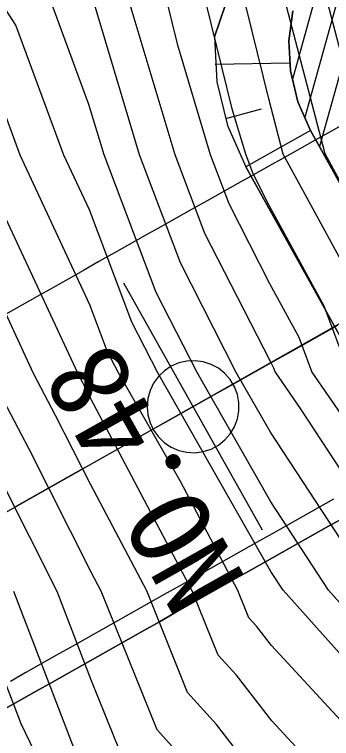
# Model space of a CAD drawing. Extents: x 42655 to 43811, y -141820 to -141156.
# Drawn here: x 43136.65 to 43145.62, y -141417.59 to -141397.14 of the extents above; entities that cross this region are included whole.
import ezdxf

# ---------------------------------------------------------------- set-up
doc = ezdxf.new("R2010")
doc.units = 0
for name, color, linetype in [('D-BMK-HTXT_1', 7, 'Continuous'), ('D-BMK_1', 7, 'Continuous'), ('D-STR', 7, 'Continuous'), ('D-STR-HTXT', 7, 'Continuous'), ('D-STR-STR2トンネル', 7, 'Continuous'), ('ZE_HICN', 7, 'Continuous'), ('ZE_LWCN', 7, 'Continuous'), ('着色', 7, 'Continuous')]:
    doc.layers.add(name, color=color, linetype=linetype)

msp = doc.modelspace()

# ---------------------------------------------------------------- linework, layer by layer
at = {"layer": 'D-BMK-HTXT_1'}
for p, q in [((43274.802, -141333.044), (43130.975, -141414.265)), ((43143.659, -141411.705), (43139.739, -141404.731))]:
    msp.add_line(p, q, dxfattribs=at)
msp.add_lwpolyline([(43140.399, -141408.218), (43140.42, -141408.45), (43140.482, -141408.675), (43140.583, -141408.885), (43140.72, -141409.073), (43140.889, -141409.234), (43141.083, -141409.363), (43141.297, -141409.454), (43141.525, -141409.506), (43141.758, -141409.517), (43141.988, -141409.485), (43142.21, -141409.413), (43142.415, -141409.303), (43142.598, -141409.158), (43142.751, -141408.982), (43142.87, -141408.782), (43142.952, -141408.564), (43142.994, -141408.335), (43142.994, -141408.101), (43142.952, -141407.872), (43142.87, -141407.654), (43142.751, -141407.454), (43142.598, -141407.278), (43142.415, -141407.133), (43142.21, -141407.023), (43141.988, -141406.951), (43141.757, -141406.919), (43141.525, -141406.93), (43141.297, -141406.982), (43141.083, -141407.073), (43140.889, -141407.202), (43140.72, -141407.363), (43140.583, -141407.551), (43140.482, -141407.761), (43140.42, -141407.986), (43140.399, -141408.218)], dxfattribs=at)
at = {"layer": 'D-BMK_1'}
msp.add_lwpolyline([(43145.788, -141405.924), (43145.352, -141406.168), (43144.915, -141406.412), (43144.479, -141406.657), (43144.043, -141406.902), (43143.607, -141407.146), (43143.171, -141407.391), (43142.735, -141407.636), (43142.299, -141407.881), (43141.863, -141408.126), (43141.428, -141408.371), (43140.992, -141408.616), (43140.556, -141408.861), (43140.12, -141409.106), (43139.685, -141409.352), (43139.249, -141409.597), (43138.813, -141409.842), (43138.378, -141410.088), (43137.942, -141410.333), (43137.507, -141410.579), (43137.071, -141410.824), (43136.635, -141411.07)], dxfattribs=at)
at = {"layer": 'D-STR'}
for p, q in [((43144.423, -141398.51), (43142.322, -141398.554)), ((43143.625, -141399.808), (43142.612, -141400.089)), ((43145.025, -141400.418), (43143.191, -141401.439)), ((43145.025, -141400.418), (43150.035, -141409.418)), ((43148.2, -141410.439), (43143.191, -141401.439))]:
    msp.add_line(p, q, dxfattribs=at)
for points in [[(43142.307, -141397.77), (43142.603, -141396.887), (43143.005, -141396.11), (43143.847, -141395.027), (43144.836, -141394.268), (43145.902, -141393.824), (43147.008, -141393.55), (43148.114, -141393.278), (43148.897, -141393.083)], [(43144.518, -141397.037), (43144.404, -141397.881), (43144.451, -141398.732)], [(43142.307, -141397.77), (43142.375, -141399.04), (43142.673, -141400.277), (43143.191, -141401.439)], [(43144.451, -141398.732), (43144.662, -141399.601), (43145.025, -141400.418)]]:
    msp.add_lwpolyline(points, dxfattribs=at)
at = {"layer": 'D-STR-HTXT'}
for p, q in [((43147.177, -141394.04), (43145.277, -141400.87)), ((43146.41, -141394.467), (43144.85, -141400.072)), ((43145.589, -141395.085), (43144.499, -141399.002))]:
    msp.add_line(p, q, dxfattribs=at)
at = {"layer": 'D-STR-STR2トンネル'}
for points in [[(43146.031, -141400.202), (43145.593, -141400.446), (43145.155, -141400.69), (43144.718, -141400.935), (43144.281, -141401.18), (43143.843, -141401.424), (43143.406, -141401.669), (43142.969, -141401.914), (43142.532, -141402.159), (43142.095, -141402.404), (43141.658, -141402.649), (43141.221, -141402.894), (43140.784, -141403.139), (43140.348, -141403.384), (43139.911, -141403.63), (43139.474, -141403.875), (43139.038, -141404.12), (43138.601, -141404.366), (43138.165, -141404.611), (43137.729, -141404.857), (43137.293, -141405.103), (43136.856, -141405.348), (43136.42, -141405.594)], [(43145.674, -141410.83), (43145.239, -141411.074), (43144.804, -141411.319), (43144.368, -141411.563), (43143.933, -141411.808), (43143.498, -141412.053), (43143.062, -141412.297), (43142.627, -141412.542), (43142.192, -141412.787), (43141.757, -141413.032), (43141.322, -141413.277), (43140.886, -141413.523), (43140.451, -141413.768), (43140.016, -141414.013), (43139.581, -141414.258), (43139.146, -141414.504), (43138.71, -141414.749), (43138.275, -141414.995), (43137.84, -141415.24), (43137.405, -141415.486), (43136.97, -141415.731), (43136.534, -141415.977)], [(43145.968, -141411.353), (43145.533, -141411.597), (43145.097, -141411.842), (43144.662, -141412.086), (43144.227, -141412.331), (43143.792, -141412.576), (43143.357, -141412.82), (43142.921, -141413.065), (43142.486, -141413.31), (43142.051, -141413.555), (43141.616, -141413.8), (43141.181, -141414.045), (43140.746, -141414.291), (43140.311, -141414.536), (43139.875, -141414.781), (43139.44, -141415.026), (43139.005, -141415.272), (43138.57, -141415.517), (43138.135, -141415.763), (43137.7, -141416.008), (43137.265, -141416.254), (43136.829, -141416.5), (43136.394, -141416.745)]]:
    msp.add_lwpolyline(points, dxfattribs=at)
at = {"layer": 'ZE_HICN'}
for points in [[(43164.284, -141418.895), (43161.139, -141417.126), (43159.184, -141416.275), (43155.119, -141414.603), (43154.086, -141414.112), (43153.652, -141413.885), (43153.016, -141413.364), (43150.606, -141411.412), (43148.978, -141409.883), (43147.144, -141407.229), (43146.118, -141404.504), (43144.251, -141401.08), (43143.841, -141399.518), (43142.715, -141394.924), (43141.74, -141391.264), (43140.342, -141388.773), (43138.687, -141385.618), (43137.581, -141383.954), (43136.3, -141382.629)], [(43155.333, -141438.004), (43155.812, -141433.818), (43156.43, -141431.836), (43157.209, -141428.129), (43157.365, -141425.669), (43156.075, -141423.318), (43154.119, -141421.235), (43152.664, -141419.528), (43150.124, -141418.199), (43149.012, -141417.289), (43145.534, -141413.399), (43143.894, -141410.906), (43141.811, -141407.254), (43140.654, -141404.988), (43139.181, -141401.104), (43138.753, -141399.676), (43137.543, -141396.396), (43136.607, -141394.953)], [(43145.016, -141438.052), (43145.353, -141433.526), (43145.834, -141431.886), (43146.049, -141429.38), (43146.564, -141425.72), (43145.24, -141424.172), (43143.947, -141422.158), (43143.228, -141420.434), (43141.798, -141418.582), (43140.68, -141417.351), (43139.101, -141413.429), (43138.815, -141412.888), (43137.049, -141409.396), (43135.932, -141407.282)]]:
    msp.add_lwpolyline(points, dxfattribs=at)
at = {"layer": 'ZE_LWCN'}
for points in [[(43164.367, -141436.421), (43166.567, -141431.788), (43167.584, -141429.556), (43169.333, -141425.613), (43168.188, -141420.901), (43167.762, -141419.457), (43164.278, -141417.448), (43161.947, -141416.138), (43159.178, -141414.933), (43155.338, -141413.353), (43154.08, -141412.801), (43151.306, -141410.555), (43148.97, -141408.362), (43148.185, -141407.224), (43146.831, -141403.632), (43145.437, -141401.074), (43143.819, -141394.919), (43142.573, -141390.245), (43141.744, -141388.766), (43138.675, -141382.915), (43138.565, -141382.75), (43138.438, -141382.619), (43137.933, -141381.729), (43134.97, -141376.473)], [(43168.565, -141418.478), (43164.271, -141416.002), (43162.755, -141415.149), (43159.171, -141413.59), (43158.558, -141413.338), (43154.073, -141411.372), (43152.007, -141409.698), (43149.366, -141407.218), (43148.962, -141406.52), (43147.545, -141402.759), (43146.623, -141401.069), (43145.554, -141397), (43144.989, -141394.914), (43144.727, -141393.808), (43143.799, -141390.698), (43143.407, -141389.225), (43143.145, -141388.76), (43142.047, -141386.665), (43140.369, -141382.61)], [(43159.19, -141417.618), (43156.819, -141416.642), (43154.091, -141415.347), (43152.946, -141414.748), (43151.267, -141413.372), (43149.905, -141412.269), (43148.985, -141411.405), (43146.104, -141407.234), (43145.404, -141405.377), (43143.855, -141402.534), (43143.396, -141401.635), (43143.187, -141401.085), (43142.815, -141399.843), (43141.612, -141394.93), (43140.906, -141392.283), (43138.94, -141388.779), (43138.7, -141388.321), (43136.596, -141385.158)], [(43135.612, -141386.361), (43137.226, -141388.787), (43138.712, -141390.877), (43140.073, -141393.302), (43140.508, -141394.935), (43141.25, -141397.965), (43142.185, -141401.09), (43142.71, -141402.473), (43143.865, -141404.735), (43144.691, -141406.25), (43145.063, -141407.239), (43148.992, -141412.926), (43149.204, -141413.126), (43149.519, -141413.38), (43152.241, -141415.611), (43154.097, -141416.582), (43158.519, -141418.682)], [(43135.447, -141388.796), (43138.724, -141393.402), (43139.24, -141394.321), (43139.404, -141394.94), (43139.686, -141396.088), (43141.184, -141401.094), (43142.025, -141403.311), (43143.876, -141406.936), (43143.977, -141407.122), (43144.023, -141407.244), (43144.73, -141408.267), (43148.097, -141413.387), (43148.999, -141414.396), (43151.535, -141416.474), (43154.103, -141417.817), (43157.657, -141419.505), (43158.478, -141420.379), (43159.21, -141421.712), (43161.074, -141425.651), (43160.551, -141427.247), (43159.64, -141431.821), (43159.263, -141433.096), (43158.159, -141436.634)], [(43156.669, -141437.998), (43156.986, -141435.226), (43158.046, -141431.828), (43159.231, -141426.186), (43159.315, -141425.764), (43159.349, -141425.66), (43159.227, -141425.402), (43157.276, -141421.849), (43155.088, -141419.517), (43154.109, -141419.052), (43150.829, -141417.337), (43149.006, -141415.842), (43146.815, -141413.393), (43143.885, -141408.937), (43142.922, -141407.249), (43141.339, -141404.15), (43140.182, -141401.099), (43138.737, -141396.271), (43138.398, -141395.351), (43138.135, -141394.946), (43133.98, -141389.243)], [(43154.19, -141436.328), (43154.638, -141432.41), (43154.815, -141431.844), (43155.038, -141430.785), (43155.362, -141425.678), (43154.873, -141424.788), (43154.132, -141423.998), (43150.33, -141419.539), (43149.418, -141419.062), (43149.019, -141418.735), (43144.252, -141413.405), (43143.903, -141412.875), (43140.7, -141407.259), (43139.968, -141405.826), (43138.767, -141402.66), (43138.042, -141401.109), (43136.689, -141397.441), (43135.079, -141394.96)], [(43151.344, -141438.023), (43152.145, -141434.321), (43152.818, -141431.853), (43152.936, -141430.367), (43153.27, -141425.688), (43149.028, -141420.709), (43148.539, -141420.137), (43148.162, -141419.549), (43143.913, -141414.963), (43143.493, -141414.42), (43143.275, -141414.179), (43142.966, -141413.411), (43141.33, -141410.316), (43139.589, -141407.264), (43139.283, -141406.665), (43138.78, -141405.339), (43136.804, -141401.115), (43135.834, -141398.486)], [(43149.106, -141437.222), (43150.567, -141431.864), (43150.881, -141427.902), (43151.038, -141425.699), (43149.041, -141423.354), (43147.439, -141421.482), (43146.205, -141419.559), (43143.923, -141417.096), (43142.928, -141415.807), (43142.41, -141415.236), (43141.678, -141413.417), (43138.792, -141407.958), (43138.575, -141407.529), (43138.438, -141407.27), (43137.997, -141406.319), (43135.566, -141401.121)], [(43146.965, -141438.043), (43147.142, -141435.672), (43148.257, -141431.874), (43148.754, -141426.072), (43148.805, -141425.709), (43146.339, -141422.827), (43144.248, -141419.568), (43143.933, -141419.228), (43142.363, -141417.195), (43141.545, -141416.294), (43140.389, -141413.423), (43138.804, -141410.423), (43137.812, -141408.462), (43137.185, -141407.276), (43135.17, -141402.927)], [(43136.433, -141462.743), (43137.553, -141458.363), (43137.996, -141456.573), (43138.216, -141455.603), (43139, -141452.2), (43139.397, -141450.404), (43139.604, -141449.657), (43141.059, -141444.234), (43141.951, -141441.701), (43143.159, -141438.061), (43143.533, -141432.457), (43143.591, -141431.896), (43143.714, -141431.56), (43143.975, -141428.197), (43144.323, -141425.73), (43144.14, -141425.517), (43143.962, -141425.239), (43142.386, -141421.463), (43141.233, -141419.97), (43139.815, -141418.409), (43138.83, -141415.961), (43137.857, -141413.435), (43136.286, -141410.329)], [(43135.393, -141413.447), (43136.828, -141417.171), (43138.855, -141421.371), (43140.102, -141422.745), (43140.702, -141423.522), (43141.629, -141425.743), (43141.394, -141428.776), (43140.244, -141431.912), (43139.7, -141437.144), (43139.638, -141438.078), (43139.437, -141438.684), (43138.943, -141440.085), (43137.421, -141444.251), (43136.53, -141447.453)], [(43136.165, -141456.582), (43136.778, -141453.879), (43137.577, -141450.413), (43137.921, -141449.121), (43138.968, -141445.358), (43139.267, -141444.242), (43140.694, -141440.192), (43141.399, -141438.069), (43141.617, -141434.8), (43141.917, -141431.904), (43142.554, -141430.168), (43142.898, -141425.737), (43141.544, -141422.493), (43140.667, -141421.357), (43138.951, -141419.466), (43138.845, -141419.204), (43136.625, -141413.441)]]:
    msp.add_lwpolyline(points, dxfattribs=at)
at = {"layer": '着色'}
msp.add_line((43144.451, -141398.732), (43144.451, -141398.732), dxfattribs=at)
msp.add_line((43144.451, -141398.732), (43144.451, -141398.732), dxfattribs=at)
for points in [[(43146.394, -141394.476), (43146.394, -141394.476), (43147.451, -141393.887), (43148.897, -141393.083), (43148.114, -141393.278), (43147.008, -141393.55), (43145.902, -141393.824), (43144.836, -141394.268), (43143.847, -141395.027), (43143.005, -141396.11), (43142.603, -141396.887), (43142.307, -141397.77), (43142.307, -141397.77)], [(43144.451, -141398.732), (43144.404, -141397.881), (43144.518, -141397.037)], [(43144.518, -141397.037), (43144.404, -141397.881), (43144.451, -141398.732)], [(43142.307, -141397.77), (43142.375, -141399.04), (43142.673, -141400.277), (43143.191, -141401.439)], [(43145.025, -141400.418), (43144.662, -141399.601), (43144.451, -141398.732)], [(43144.451, -141398.732), (43144.662, -141399.601), (43145.025, -141400.418)], [(43150.035, -141409.418), (43150.035, -141409.418), (43145.025, -141400.418), (43145.025, -141400.418)], [(43145.025, -141400.418), (43145.025, -141400.418), (43150.035, -141409.418)], [(43143.191, -141401.439), (43143.191, -141401.439), (43148.2, -141410.439), (43148.2, -141410.439)], [(43148.057, -141410.182), (43143.339, -141401.706), (43142.969, -141401.914), (43142.532, -141402.159), (43142.095, -141402.404), (43141.658, -141402.649), (43141.221, -141402.894), (43140.784, -141403.139), (43140.348, -141403.384), (43139.911, -141403.63), (43139.474, -141403.875), (43139.038, -141404.12), (43138.601, -141404.366), (43138.165, -141404.611), (43137.729, -141404.857), (43137.293, -141405.103), (43136.856, -141405.348), (43136.42, -141405.594)], [(43136.394, -141416.745), (43136.829, -141416.5), (43137.265, -141416.254), (43137.7, -141416.008), (43138.135, -141415.763), (43138.57, -141415.517), (43139.005, -141415.272), (43139.44, -141415.026), (43139.875, -141414.781), (43140.311, -141414.536), (43140.746, -141414.291), (43141.181, -141414.045), (43141.616, -141413.8), (43142.051, -141413.555), (43142.486, -141413.31), (43142.921, -141413.065), (43143.357, -141412.82), (43143.792, -141412.576), (43144.227, -141412.331), (43144.662, -141412.086), (43145.097, -141411.842), (43145.533, -141411.597), (43145.968, -141411.353)]]:
    msp.add_lwpolyline(points, dxfattribs=at)

# ---------------------------------------------------------------- texts
at = {"layer": 'D-BMK-HTXT_1'}
msp.add_text('NO.48', height=2.3065, rotation=119.3448, dxfattribs=at).set_placement((43143.212, -141413.103))

doc.saveas('drawing.dxf')
